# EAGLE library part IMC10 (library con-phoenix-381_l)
Invertierter Mini-Combicon 3.81mm horizontal 10-polig IMC 1,5/10-G-3,81 (ohne Gegenstecker)
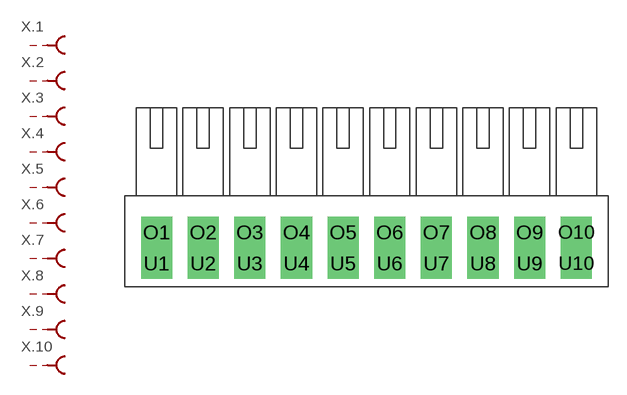
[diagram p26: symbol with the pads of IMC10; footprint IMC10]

Designator prefix X; gates .5=MCBU .4=MCBU .3=MCBU .2=MCBU .1=MCBU .6=MCBU .7=MCBU .8=MCBU .9=MCBU .10=MCBU

## IMC10  [IMC10]
O1  .1:S  pas
O2  .2:S  pas
O3  .3:S  pas
O4  .4:S  pas
O5  .5:S  pas
O6  .6:S  pas
O7  .7:S  pas
O8  .8:S  pas
O9  .9:S  pas
O10  .10:S  pas
U1  .1:SK  pas
U2  .2:SK  pas
U3  .3:SK  pas
U4  .4:SK  pas
U5  .5:SK  pas
U6  .6:SK  pas
U7  .7:SK  pas
U8  .8:SK  pas
U9  .9:SK  pas
U10  .10:SK  pas

## Footprint IMC10 (pad centres in mm)
Mini-Combicon 3.81mm horizontal 10-polig invertiert (ohne Gegenstecker)
drill 1.3 pad 2.54 square: O1 -17.145,1.27; O2 -13.335,1.27; O3 -9.525,1.27; O4 -5.715,1.27; O5 -1.905,1.27; O6 1.905,1.27; O7 5.715,1.27; O8 9.525,1.27; O9 13.335,1.27; O10 17.145,1.27; U1 -17.145,-1.27; U2 -13.335,-1.27; U3 -9.525,-1.27; U4 -5.715,-1.27; U5 -1.905,-1.27; U6 1.905,-1.27; U7 5.715,-1.27; U8 9.525,-1.27; U9 13.335,-1.27; U10 17.145,-1.27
